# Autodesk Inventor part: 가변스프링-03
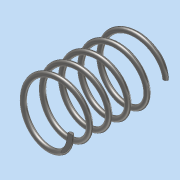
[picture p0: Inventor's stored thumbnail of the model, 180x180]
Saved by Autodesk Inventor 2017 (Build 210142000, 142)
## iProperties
Part Number: 가변스프링-03
Material: 강철, 연강
Document SubType Name: Modeling
Designer: MRC
Mass: 8.42454 g
Surface Area: 21.7273 cm^2
Volume: 1.07319 cm^3
Density: 7.85 g/cm^3
Appearance: 반연마
Author: MRC
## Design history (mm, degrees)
sketch "스케치1"
  geometry: L1 (0, 0)-(0, 37.411); L2 (0, 0)-(11, 0); L3 (0, 37.411)-(11, 37.411); C1 r 1 at (11, 0)
  constraints: 6 end point, 2 horizontal, 1 centre point, 1 coincident, 1 vertical
  dimensions: "d0" = 37.4112 distance of L1.start L1.end (derived); "d1" = 11 distance of L1.start L2.end; "d2" = 2 diameter of C1
feature "코일1" sketch "스케치1" pitch "d3" = 10; turns "d5" = 5; dims "d4" = 37.4112 (= d0), "d6" = 0, angle "d7" = 90 deg, angle "d8" = 90 deg, "d9" = 0, "d10" = 0
sketch "스케치2"
  geometry: L1 (37.411, 15)-(0, 15); L2 (0, 15)-(0, -15); L3 (0, -15)-(37.411, -15); L4 (37.411, -15)-(37.411, 15); 2 further points
  constraints: 8 end point, 2 parallel, 1 coincident, 1 horizontal, 1 midpoint, 1 perpendicular
  dimensions: "d11" = 37.4112 distance of L1.start L1.end (= d0); "d12" = 30 distance of L3.end L1.start
extrude "돌출1" sketch "스케치2" stored distance "d13" = 0; taper "d14" = 0 deg
node "솔리드1"
